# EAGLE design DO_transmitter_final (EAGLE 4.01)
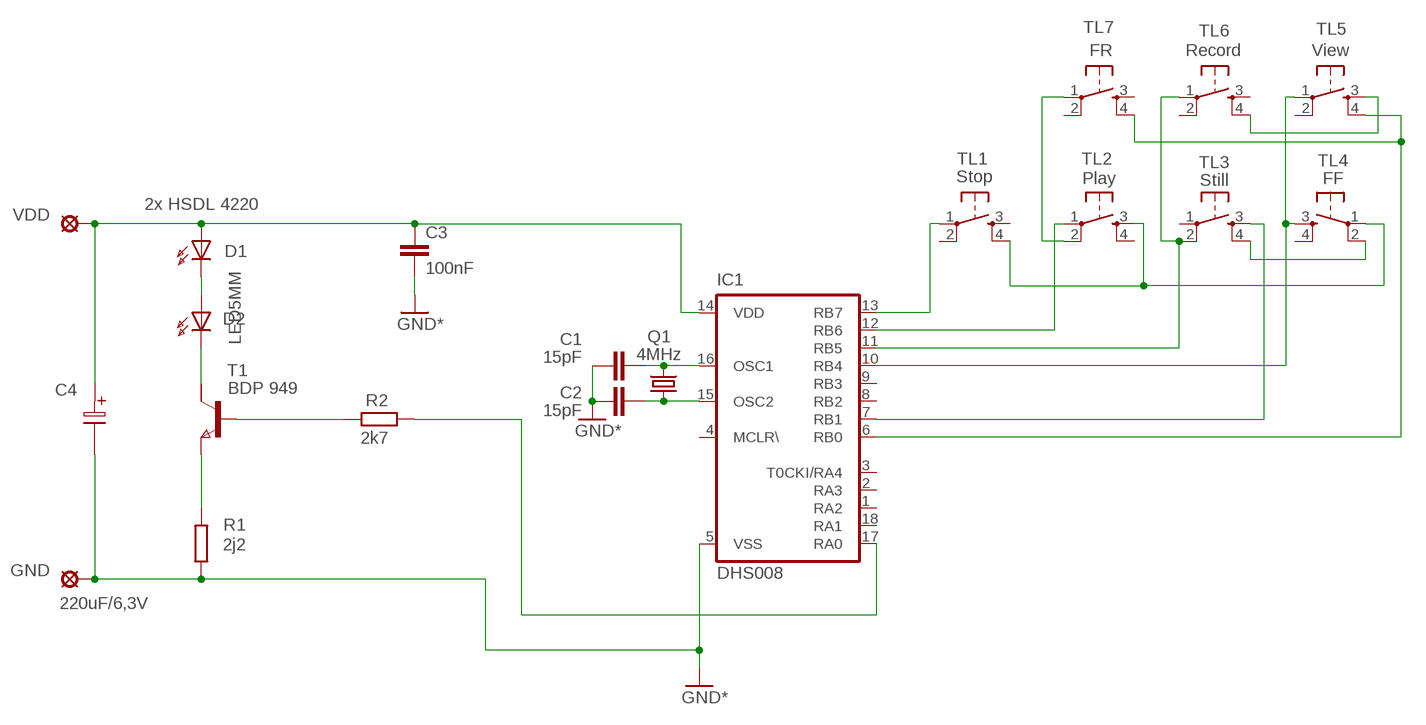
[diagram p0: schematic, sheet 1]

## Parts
C1  15pF  C-EUC1206  [C1206]
C2  15pF  C-EUC1206  [C1206]
C3  100nF  C-EUC1206  [C1206]
C4  220uF/6,3V  E5X11  [E50]
D1  2x HSDL 4220  LED5MM  [LED5MM]
D2  LED5MM  [LED5MM]
GND  GND  LSP10  [LSP10]
IC1  DHS008  PIC16F83SO  [SO-18W]
Q1  4MHz  HC49U-V  [HC49U-V]
R1  2j2  R-EU_M1206  [M1206]
R2  2k7  R-EU_M1206  [M1206]
T1  BDP 949  NPNSOT223  [SOT223]
TL1  Stop  TL_SMD*  [SWITCH]
TL2  Play  TL_SMD*  [SWITCH]
TL3  Still  TL_SMD*  [SWITCH]
TL4  FF  TL_SMD*  [SWITCH]
TL5  View  TL_SMD*  [SWITCH]
TL6  Record  TL_SMD*  [SWITCH]
TL7  FR  TL_SMD*  [SWITCH]
VDD  LSP10  [LSP10]

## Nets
GND: C1.2 C2.2 C3.1 C4.2 GND.MP IC1.5(VSS) R1.1 ; supply symbol labelled GND*
N$1: C1.1 IC1.16(OSC1) Q1.2
N$2: C2.1 IC1.15(OSC2) Q1.1
N$3: IC1.17(RA0) R2.1
N$5: R2.2 T1.1(B)
N$6: D2.K(C) T1.2(C1)
N$8: D1.K(C) D2.A
N$9: TL5.3 TL6.4
N$10: IC1.10(RB4) TL4.3 TL5.1
N$11: IC1.6(RB0) TL5.4 TL7.4
N$12: IC1.11(RB5) TL3.2 TL6.1
N$13: IC1.7(RB1) TL3.3
N$14: IC1.12(RB6) TL2.1
N$15: IC1.13(RB7) TL1.1
N$16: TL3.4 TL4.2
N$18: TL1.4 TL2.3 TL4.1
N$19: R1.2 T1.3(E)
N$20: TL2.2 TL7.1
VDD: C3.2 C4.1 D1.A IC1.14(VDD) VDD.MP
Unconnected: IC1.1(RA2) IC1.2(RA3) IC1.3(T0CKI/RA4) IC1.4(MCLR\) IC1.8(RB2) IC1.9(RB3) IC1.18(RA1) T1.4(C2) TL1.2 TL1.3 TL2.4 TL3.1 TL4.4 TL5.2 TL6.2 TL6.3 TL7.2 TL7.3

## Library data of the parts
C1-C3 = rcl:C-EU: CAPACITOR, European symbol
C4 = GM99:E5X11
D1 D2 = led:LED5MM: LED
GND VDD = solpad:LSP10: SOLDER PAD
IC1 = microchip:PIC16F8*: MICROCONTROLLER 8-Bit PIC16F8X Family - CMOS Flash/EEPROM Pin Compatible : PIC16F83, PIC16CR83, PIC16F84A, PIC16CR84 see also PIC16C*
Q1 = crystal:HC49U-V: CRYSTAL
R1 R2 = rcl:R-EU_: RESISTOR, European symbol
T1 = zetex:NPNSOT223: NPN TRANSISTOR
TL1-TL7 = DH_servis:TL_SMD

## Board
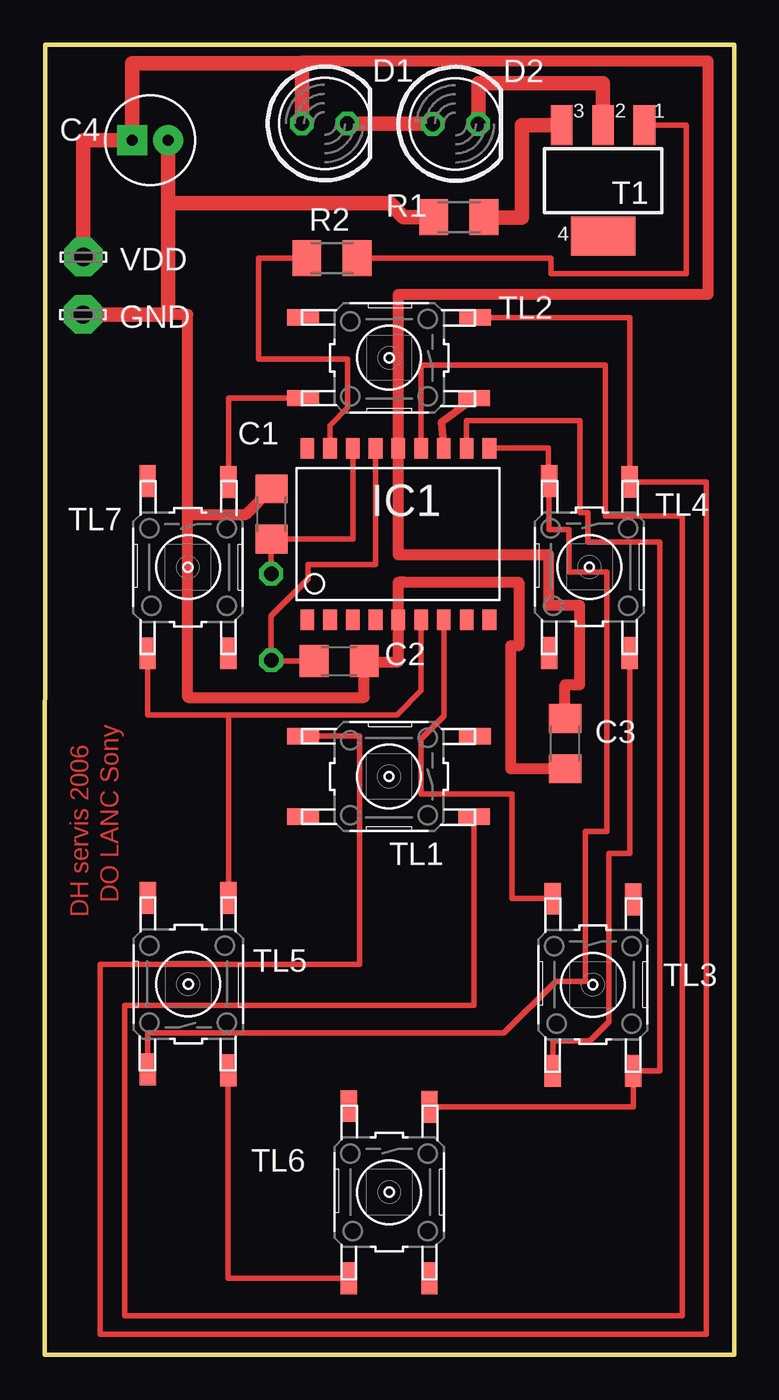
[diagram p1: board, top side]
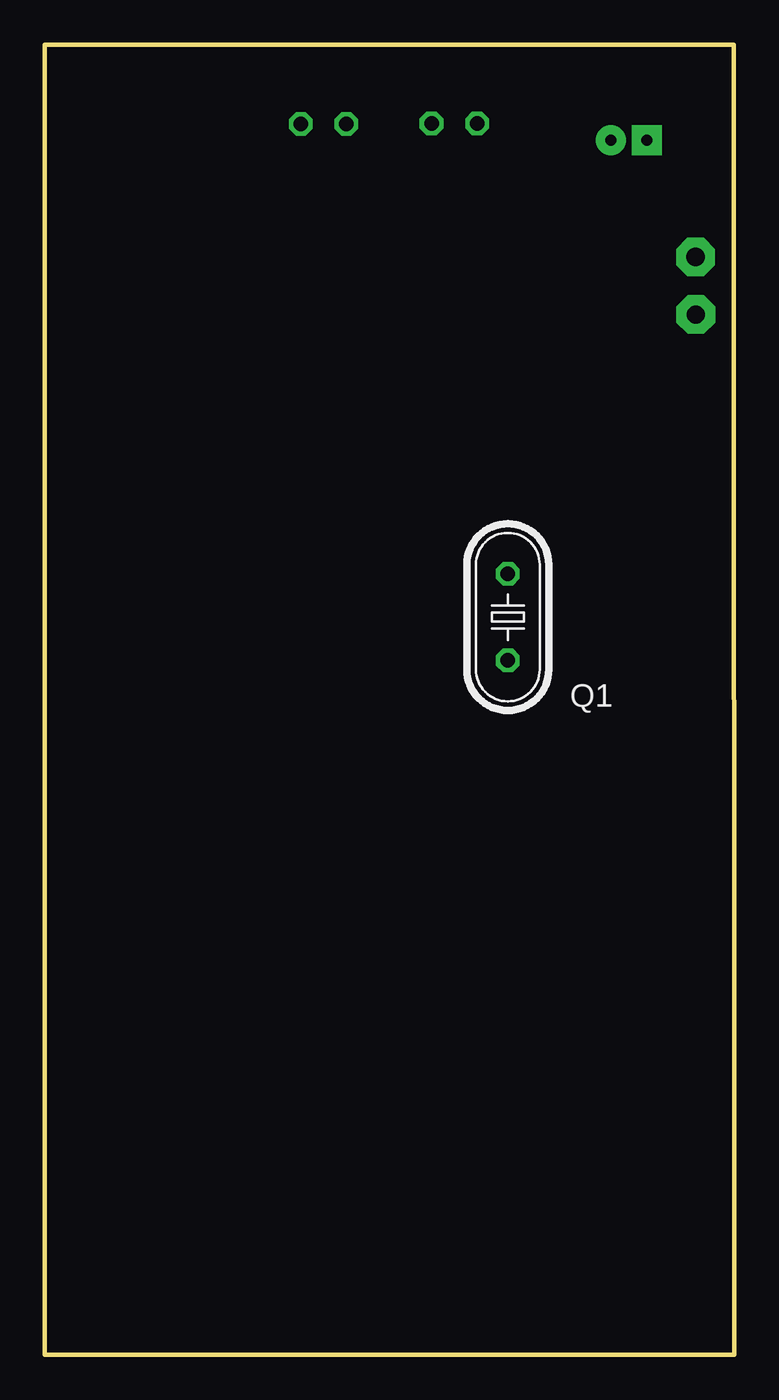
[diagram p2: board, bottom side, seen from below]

Size 38.45 x 73.05 mm. Coordinates in mm from the lower left corner, seen from the top.
Outline: 0,0 2.51,0 38.45,0 38.45,73.05 0.01,73.05 0,0
Copper layers used: Top

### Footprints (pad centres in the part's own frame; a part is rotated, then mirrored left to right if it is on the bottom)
C1206 = smd 1.6 x 1.8: 1 -1.4,0; 2 1.4,0
E50 = drill 0.61 pad 1.676 square: 1 0,0 | drill 0.61 pad 1.676 round: 2 2,0
LED5MM = drill 0.813 octagon: A -1.27,0; K 1.27,0
LSP10 = drill 1.016 pad 2.159 octagon: MP 0,0
SO-18W = smd 0.762 x 1.143: 1 -5.08,-4.788; 2 -3.81,-4.788; 3 -2.54,-4.788; 4 -1.27,-4.788; 5 0,-4.788; 6 1.27,-4.788; 7 2.54,-4.788; 8 3.81,-4.788; 9 5.08,-4.788; 10 5.08,4.788; 11 3.81,4.788; 12 2.54,4.788; 13 1.27,4.788; 14 0,4.788; 15 -1.27,4.788; 16 -2.54,4.788; 17 -3.81,4.788; 18 -5.08,4.788
HC49U-V = drill 0.813 octagon: 1 -2.413,0; 2 2.413,0
M1206 = smd 1.6 x 2: 1 -1.4,0; 2 1.4,0
SOT223 = smd 1.219 x 2.235: 1 -2.311,-3.099; 2 0,-3.099; 3 2.311,-3.099 | smd 3.6 x 2.2: 4 0,3.099
SWITCH = smd 1.778 x 0.914: 1 -4.75,2.25; 2 4.8,2.25; 3 -4.8,-2.25; 4 4.8,-2.25

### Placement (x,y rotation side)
C1  12.65,46.89 90 top
C2  16.42,38.69 0 top
C3  29.02,34.08 90 top
C4  4.87,67.73 0 top
D1  15.61,68.66 0 top
D2  22.9,68.64 0 top
GND  2.13,58.01 0 top
IC1  19.72,45.77 0 top
Q1  12.63,41.13 90 bottom
R1  23.1,63.45 0 top
R2  16.01,61.15 0 top
T1  31.14,65.48 180 top
TL1  19.2,32.25 180 top
TL2  19.21,55.6 180 top
TL3  30.57,20.63 270 top
TL4  30.38,43.93 270 top
TL5  8,20.66 90 top
TL6  19.21,9.06 270 top
TL7  7.99,43.92 270 top
VDD  2.15,61.22 0 top

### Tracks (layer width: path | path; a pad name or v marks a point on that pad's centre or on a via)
GND
  Top 0.61: 17.82,38.64 17.8,38.64 | 17.82,38.64 C2.2 | 17.82,38.64 17.82,36.65 7.98,36.65 7.98,46.87 | C1.2 11.22,46.87 8.37,46.87 | 8.37,46.87 8.51,46.87 | 7.98,46.87 8.37,46.87 | C3.1 25.98,32.68 25.98,39.52 26.44,39.52 26.44,43.08 25.88,43.08 | 6.88,58.02 6.81,58.02 | 6.88,58.02 6.88,58.01 | 7.98,46.87 7.98,58.02 6.88,58.02 | 20.07,43.08 25.88,43.08 | 20.07,43.08 19.76,43.08 | 20.07,43.08 19.72,43.08 IC1.5 19.72,38.64 17.82,38.64 | 25.88,43.08 25.98,43.08
  Top 0.813: GND.MP 6.88,58.01 6.88,61.52 | R1.1 20.02,63.45 19.25,64.21 6.88,64.21 6.88,63.38 | 6.88,61.52 6.88,61.78 | 6.88,63.38 6.88,66.47 | 6.88,61.52 6.88,63.38 | 6.88,66.47 6.88,66.66 | C4.2 6.88,67.72 6.88,66.47
N$1
  Top 0.305: 17.18,46.97 IC1.16 | C1.1 | C1.1 17.18,45.49 17.18,46.97 | Q1.2 12.63,45.47 C1.1 | 17.18,46.97 17.18,47 | 17.18,46.97
N$2
  Top 0.305: IC1.15 18.45,44.07 14.68,44.07 14.68,43.26 13.18,41.76 | 13.18,41.76 13.13,41.71 | 13.18,41.76 12.63,41.2 Q1.1 12.62,38.69 C2.1
N$3
  Top 0.305: R2.1 11.94,61.15 11.94,55.53 16.89,55.53 16.89,52.81 15.9,51.82 IC1.17
N$5
  Top 0.305: R2.2 28.22,61.15 28.22,60.3 35.79,60.3 35.79,68.46 | 35.79,68.46 35.79,68.58 | T1.1 35.79,68.58 35.79,68.46
N$6
  Top 0.813: D2.K 24.18,68.64 24.18,70.92 31.01,70.92 | 31.01,70.92 31.14,70.92 | T1.2 31.14,70.92 31.01,70.92
N$8
  Top 0.813: D1.K 16.89,68.64 D2.A
N$9
  Top 0.305: 10.24,15.87 10.24,15.88 | 10.24,15.87 TL5.3 | TL6.4 10.24,4.27 10.24,15.87
N$10
  Top 0.305: IC1.10 28.09,50.56 28.09,48.73 TL4.3 28.13,46.03 29.23,46.03 29.23,43.64 31.34,43.64 31.34,36.22 | 31.34,36.22 31.34,29.19 30.15,29.19 30.15,20.83 28.5,20.83 25.6,17.93 5.75,17.93 TL5.1 | 31.34,36.22 31.34,37.26
N$11
  Top 0.305: TL7.4 5.74,35.69 10.26,35.69 | 10.26,35.69 19.63,35.69 20.98,37.04 20.98,41 | 20.98,41 | 20.98,41 IC1.6 | TL5.4 10.25,35.69 10.26,35.69
N$12
  Top 0.305: TL6.1 32.82,13.82 TL3.2 34.31,15.83 34.31,45.32 30.3,45.32 30.3,46.97 29.84,46.97 29.84,52.1 23.52,52.1 IC1.11 | IC1.11 23.52,50.52 | IC1.11
N$13
  Top 0.305: IC1.7 22.26,35.62 20.98,34.34 20.98,31.27 26.06,31.27 26.06,25.43 TL3.3
N$14
  Top 0.406: IC1.12 22.12,52.01 22.2,52.08 TL2.1
N$15
  Top 0.305: TL1.1 23.95,19.48 4.45,19.48 4.45,2.16 35.56,2.16 35.56,46.76 31.27,46.76 31.27,55.2 20.98,55.2 IC1.13 | IC1.13 20.98,50.45 | IC1.13
N$16
  Top 0.305: TL4.2 32.63,27.97 31.47,27.97 31.47,27.69 | 28.32,15.73 | TL3.4 28.32,15.73 | 28.32,15.73 28.35,15.75 28.35,17.5 30.4,17.5 31.47,18.57 31.47,27.69 | 31.47,27.69 31.47,27.71
N$18
  Top 0.305: TL1.4 17.55,34.5 17.55,21.77 3.1,21.77 3.1,1.15 36.91,1.15 36.91,48.67 32.64,48.67 | 32.64,48.67 32.63,48.67 TL4.1 32.64,48.67 | TL2.3 32.64,57.85 32.64,48.67
N$19
  Top 0.813: 24.5,63.43 24.49,63.43 | R1.2 24.5,63.43 | 26.62,68.3 26.62,63.43 24.5,63.43 | 26.62,68.3 26.62,68.58 | T1.3 26.62,68.58 26.62,68.3
N$20
  Top 0.305: TL7.1 10.26,48.67 10.26,53.35 TL2.2
VDD
  Top 0.61: C3.2 29.02,37.37 29.84,37.37 29.84,41.79 28.12,41.79 28.12,44.6 19.72,44.6 IC1.14 19.72,59.13 37.01,59.13 37.01,72.14 14.33,72.14 14.33,68.68 | 14.33,68.66 D1.A
  Top 0.813: 14.33,68.66 14.33,68.68 14.35,68.68 14.35,72.04 4.87,72.04 C4.1 4.87,67.74 | 4.87,67.74 4.88,67.74 | VDD.MP 2.15,67.74 4.87,67.74

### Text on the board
Top: DO LANC Sony | DH servis 2006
